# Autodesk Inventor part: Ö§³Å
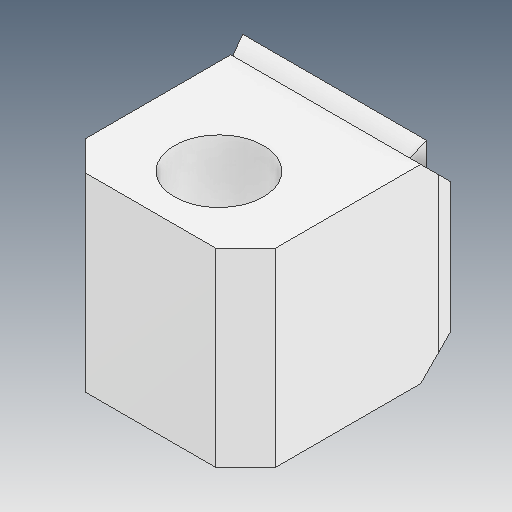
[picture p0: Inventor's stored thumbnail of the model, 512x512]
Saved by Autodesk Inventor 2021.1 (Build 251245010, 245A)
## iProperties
Created: 2021-05
Part Number: Ö§³Å
Material: Ogólny
Document SubType Name: Modeling
Designer: user
Density: 1 g/cm^3
Appearance: Domyślna
Author: user
Revision Number: ÈÎºÎ
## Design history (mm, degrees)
feature "ÊäÈë1"
feature "ÊäÈë2"
feature "ÊäÈë3"
node "Bryła1"
node "Bryła2"
node "Bryła3"
